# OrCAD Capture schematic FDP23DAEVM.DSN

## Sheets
1 PAGE3: size A; title: Adapter board-Power
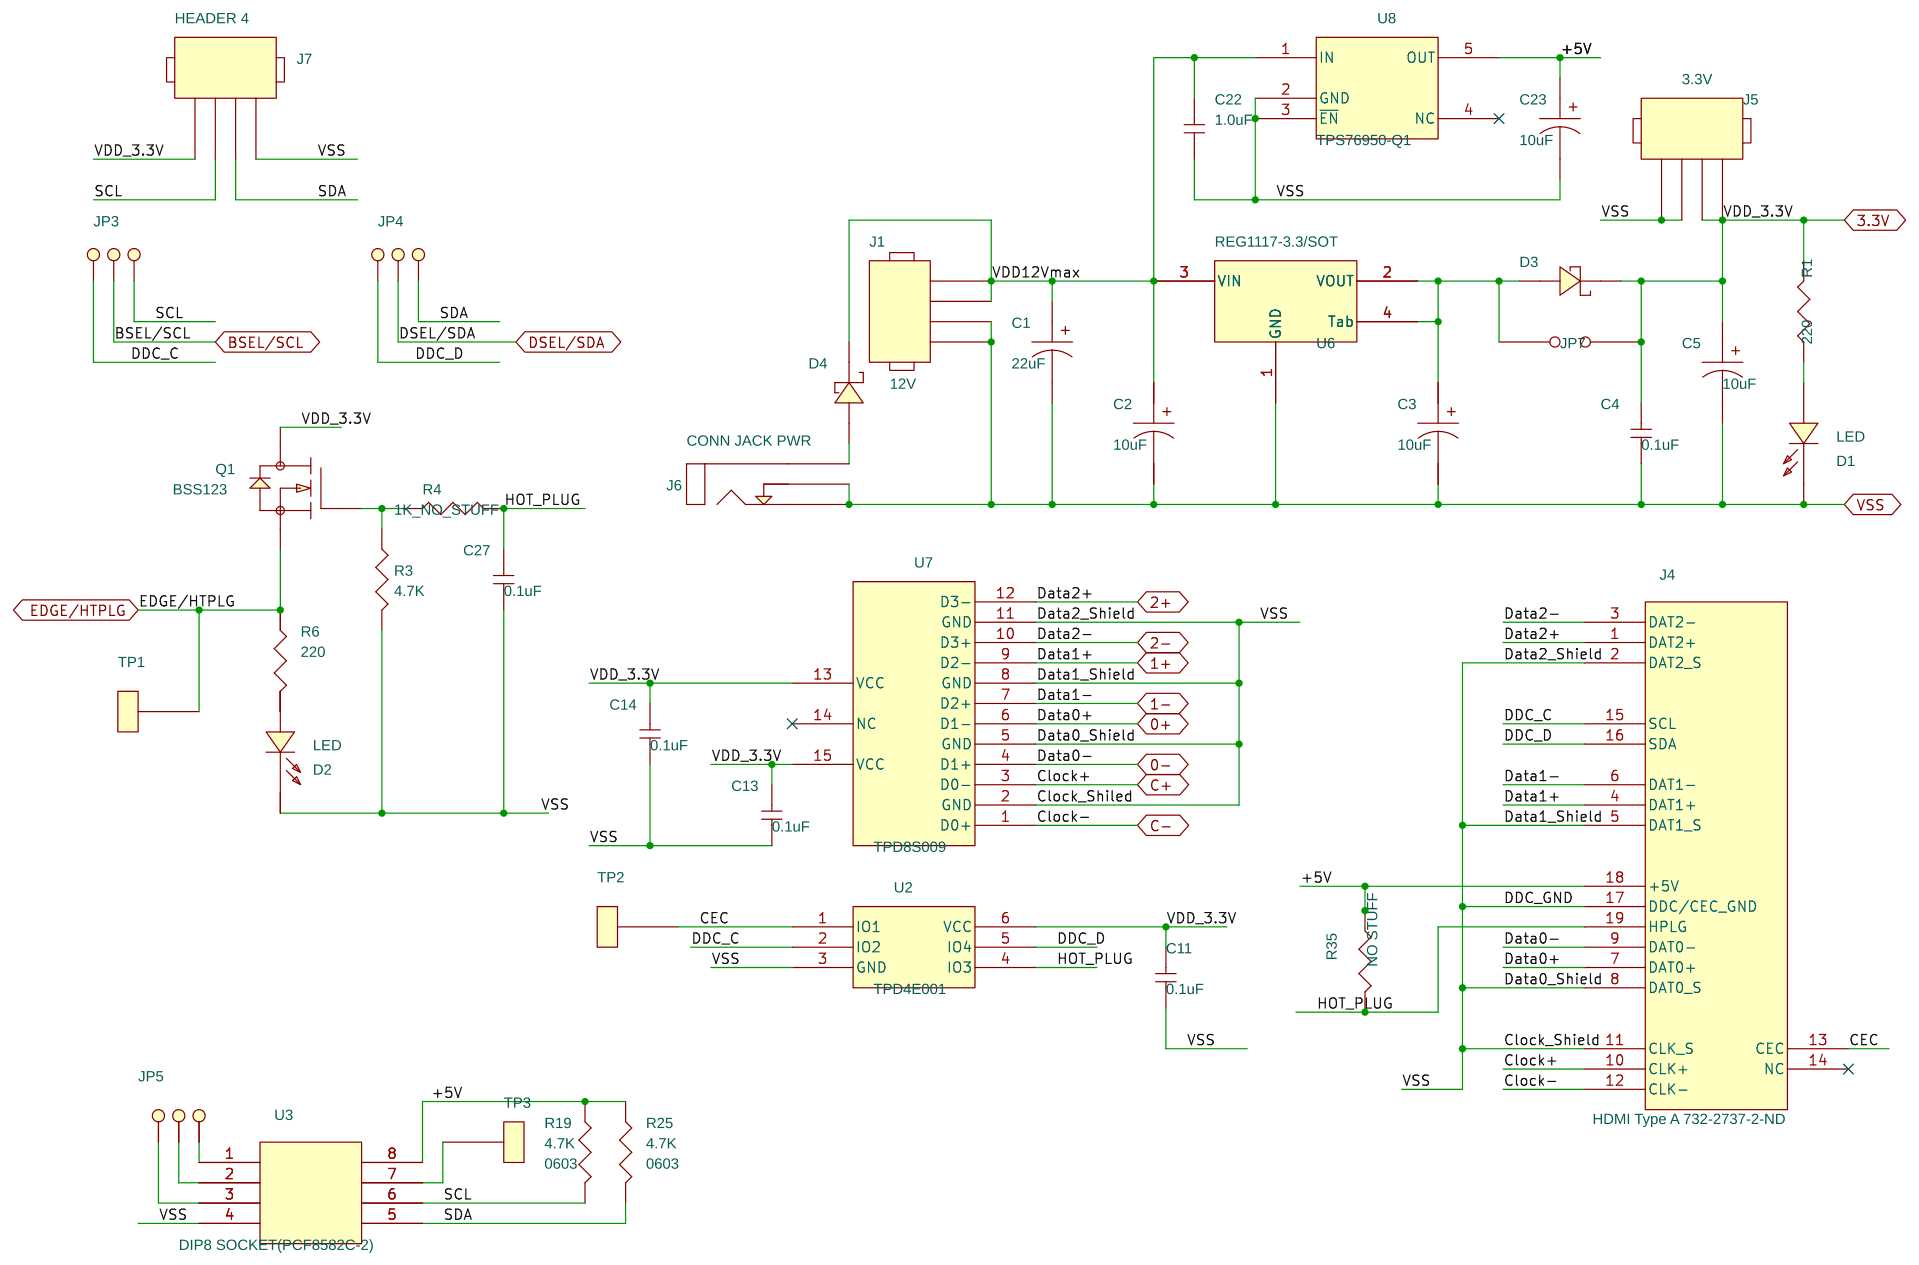
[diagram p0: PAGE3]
2 PAGE2: size A; title: Adapter board- DS90CF386
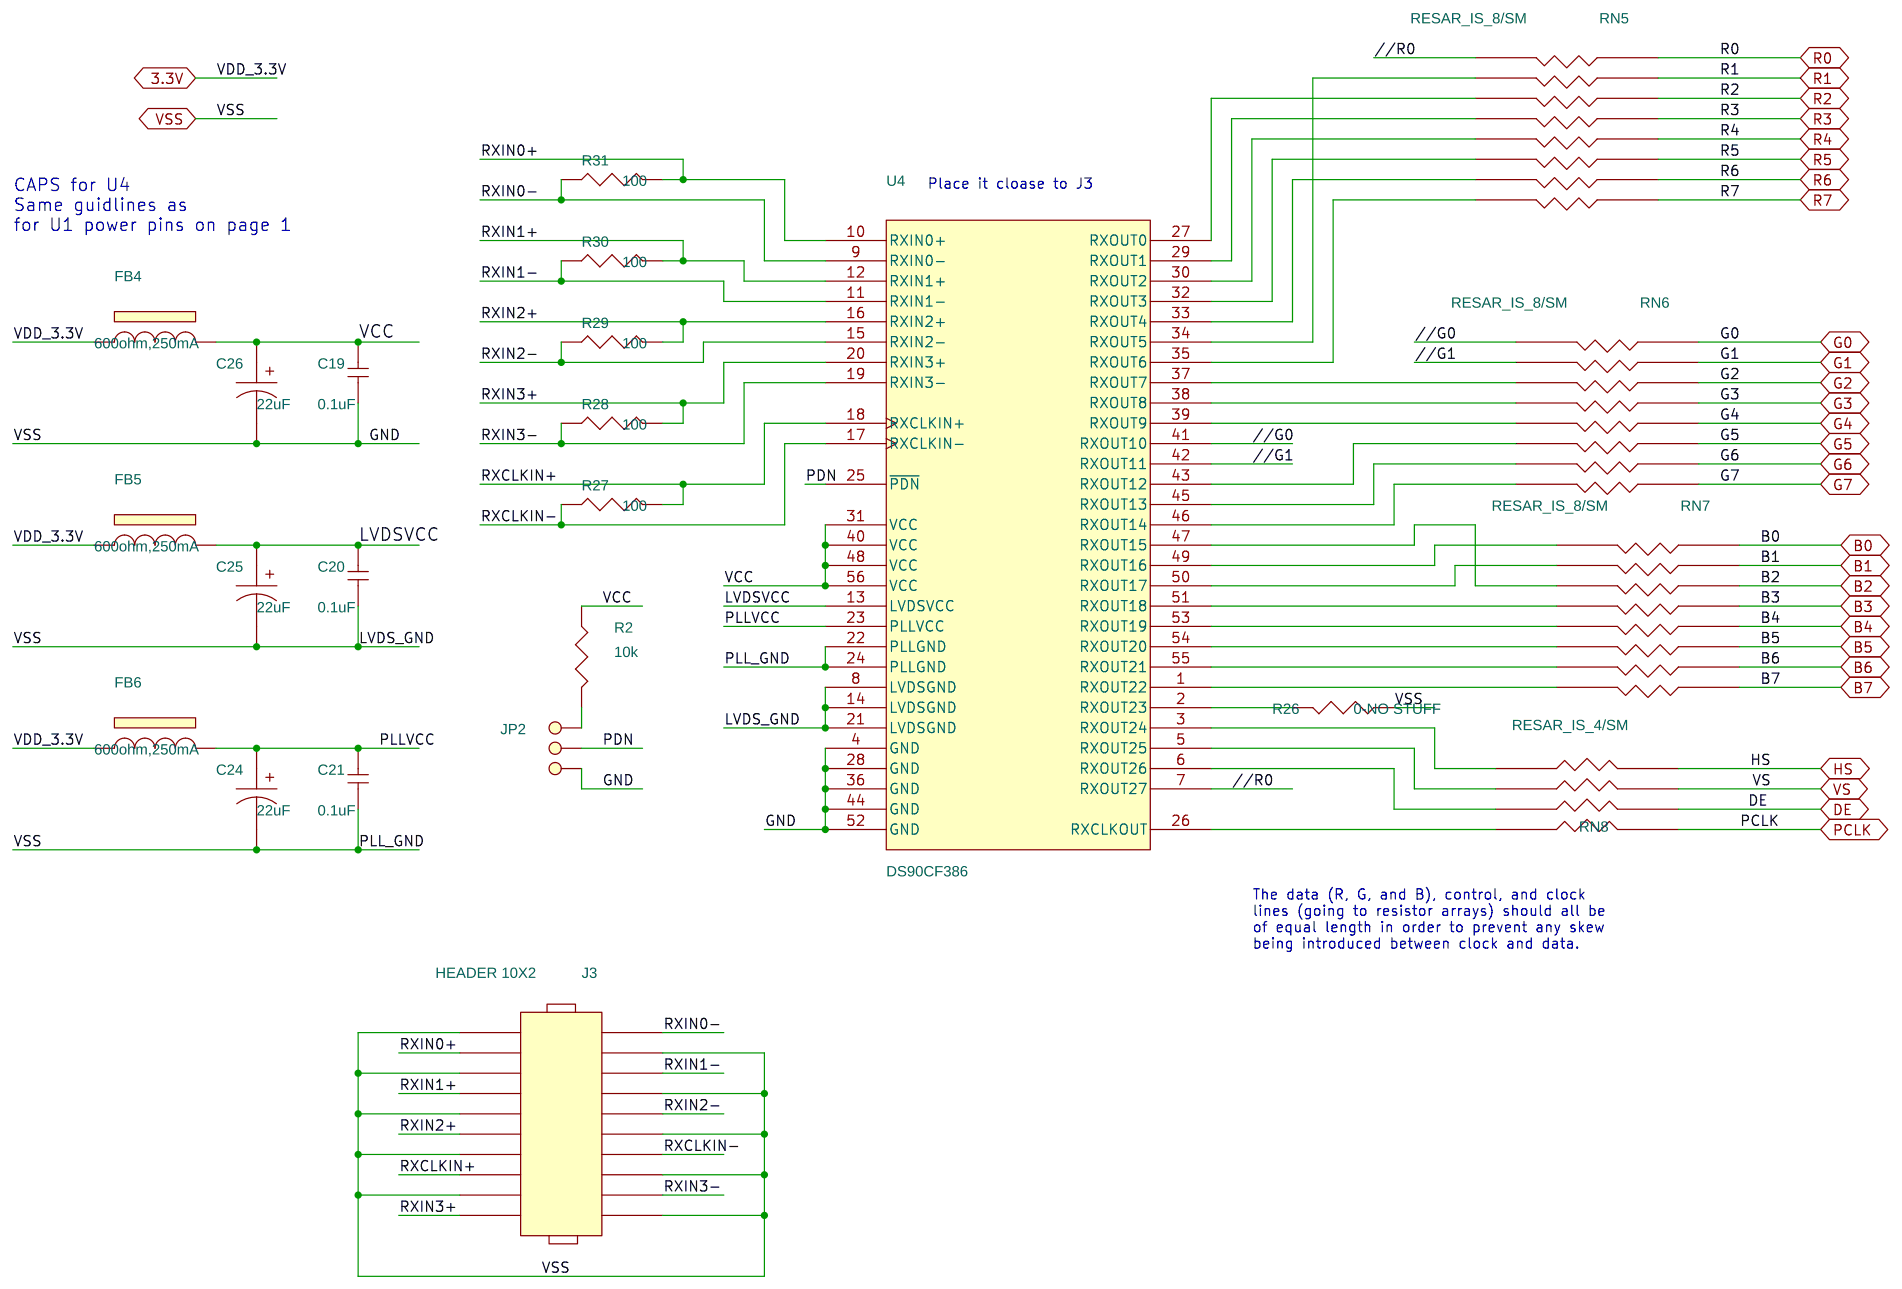
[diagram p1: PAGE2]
3 PAGE1: size B; title: Adapter Board-TFP410
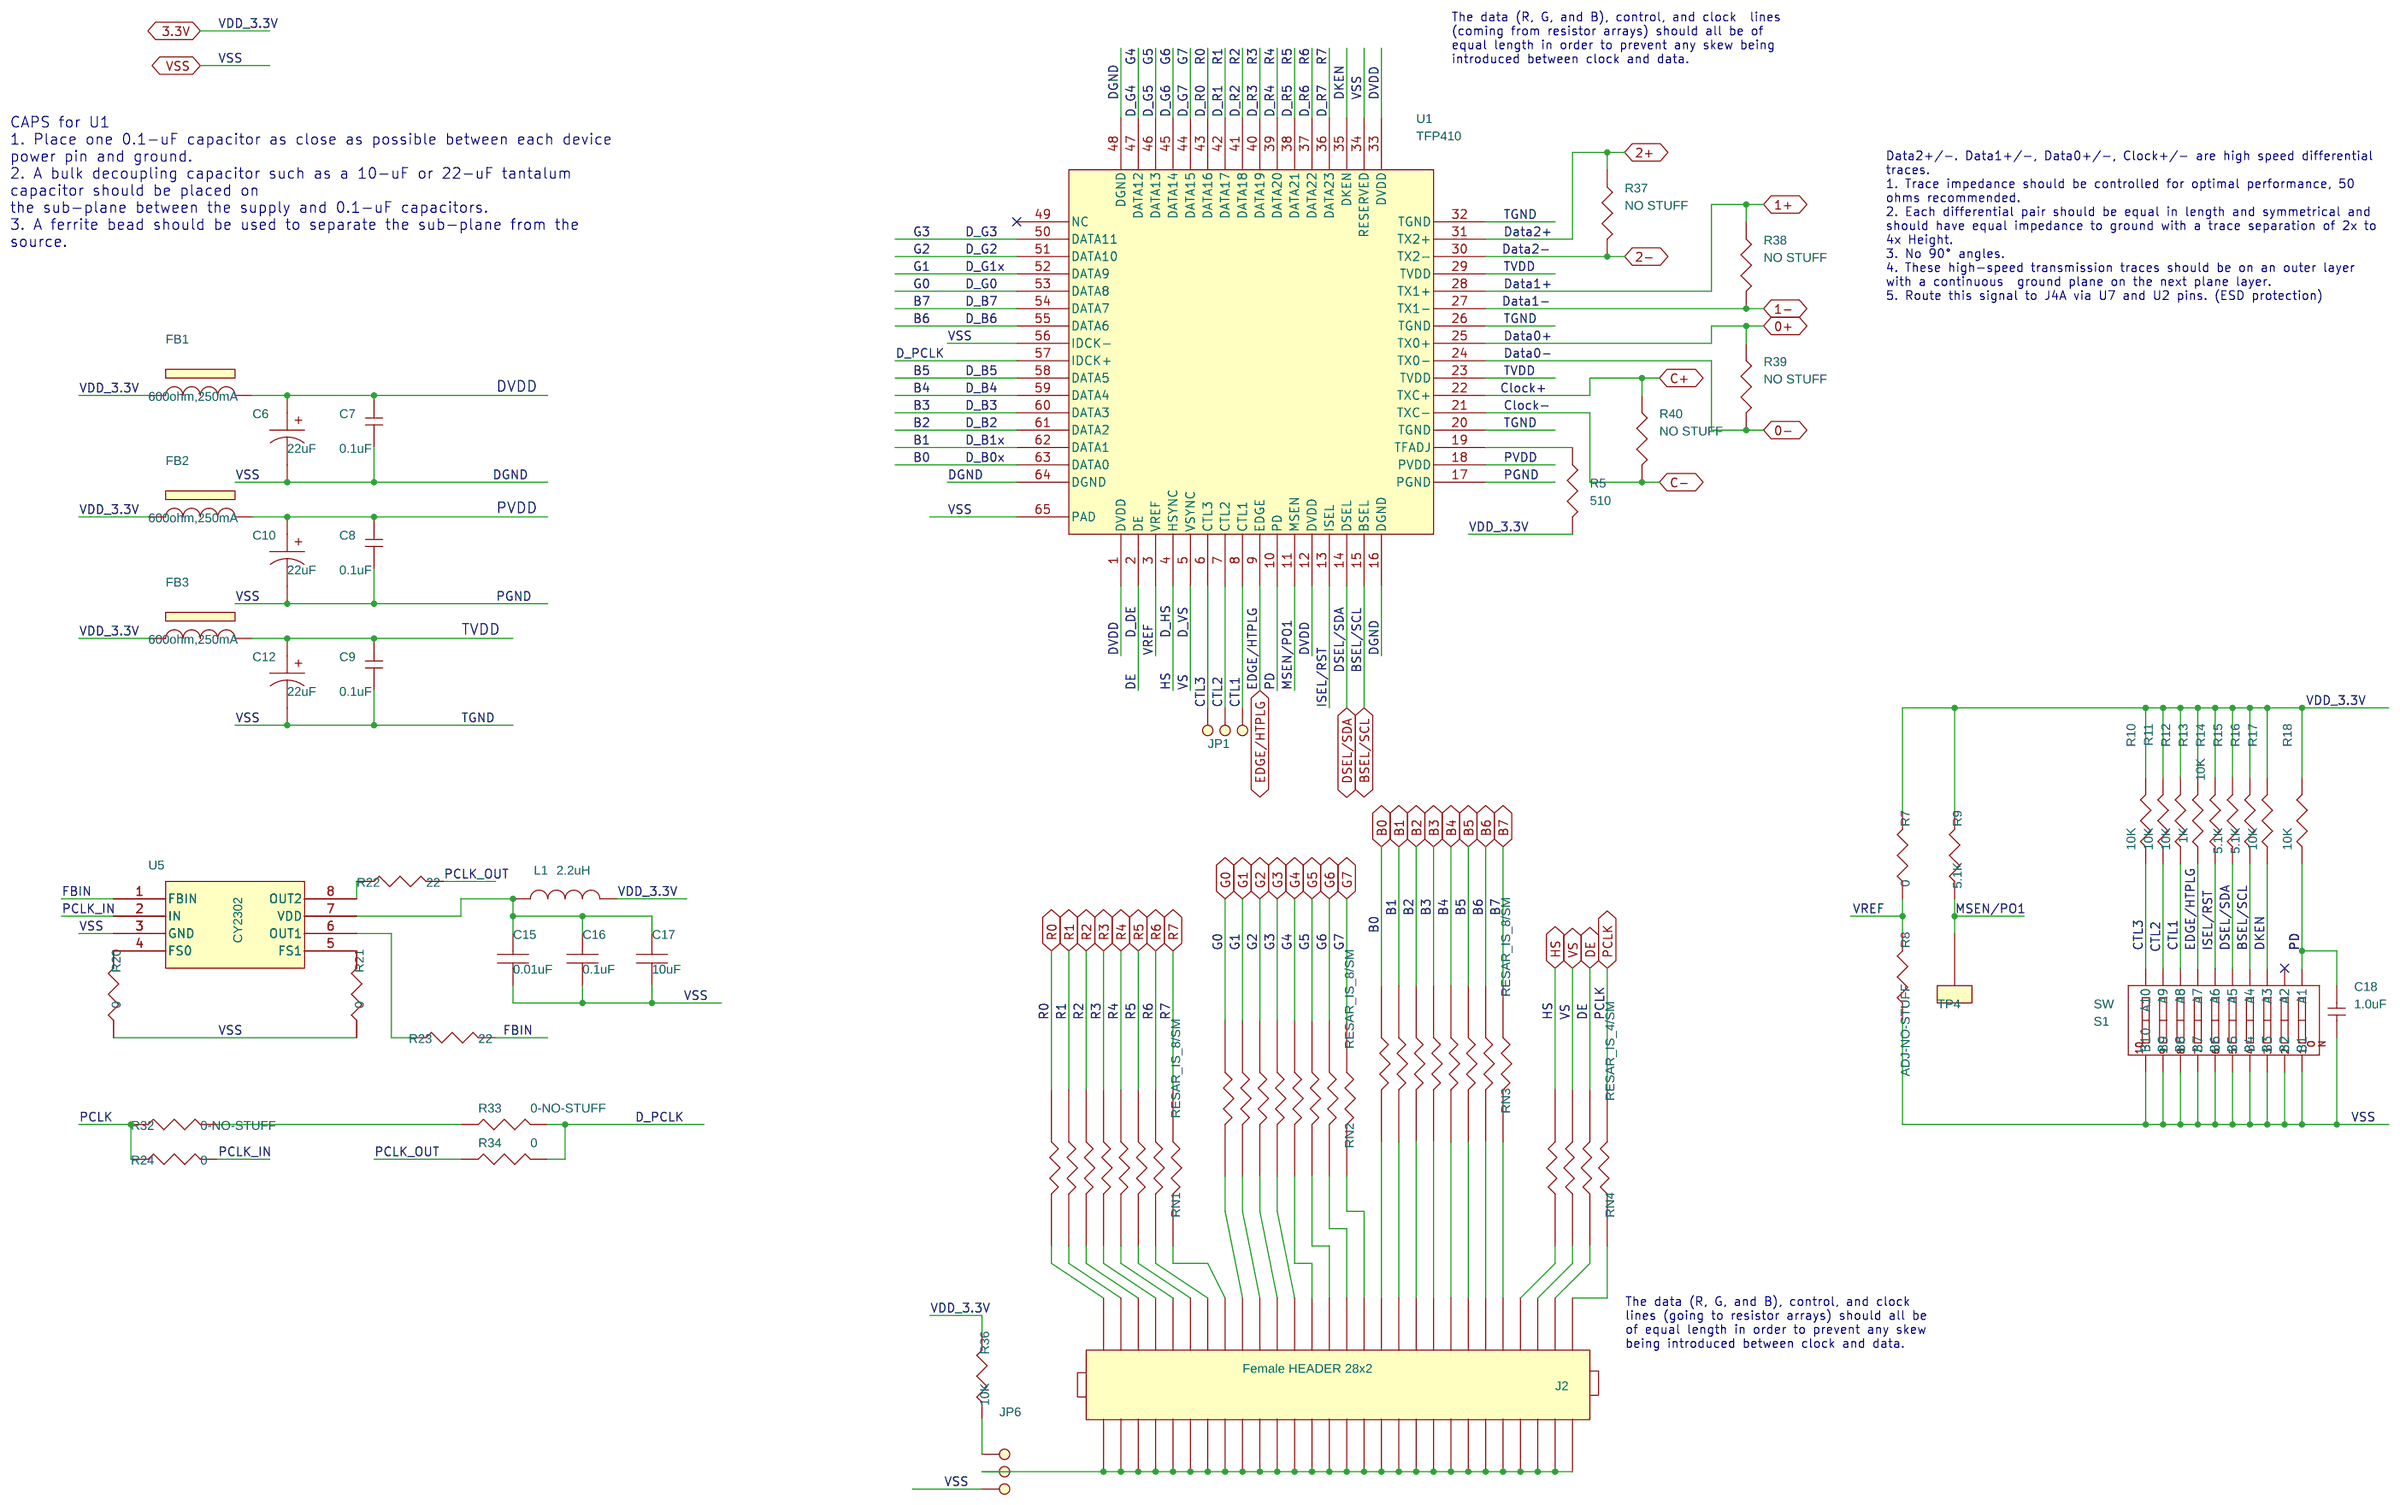
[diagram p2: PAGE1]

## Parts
sheet PAGE1
C6  22uF  [1206]
C7  0.1uF  [0201]
C8  0.1uF  [0201]
C9  0.1uF  [0201]
C10  22uF  [1206]
C12  22uF  [1206]
C15  0.01uF  [0603]
C16  0.1uF  [0603]
C17  10uF  [0612]
C18  1.0uF  [0402]
FB1  600ohm,250mA  [0402]
FB2  600ohm,250mA  [0402]
FB3  600ohm,250mA  [0402]
J2  Female HEADER 28x2  [HEADER_28X2_female]
JP1  3-Pin Header  [Header_3P]
JP6  3-Pin Header  [Header_3P]
L1  2.2uH  [1007]
R5  510  [0402]
R7  0  [0402]
R8  ADJ-NO-STUFF  [0603]
R9  5.1K  [0402]
R10  10K  [0402]
R11  10K  [0402]
R12  10K  [0402]
R13  1K  [0402]
R14  10K  [0402]
R15  5.1K  [0402]
R16  5.1K  [0402]
R17  10K  [0402]
R18  10K  [0402]
R20  0  [0402]
R21  0  [0402]
R22  22  [0402]
R23  22  [0402]
R24  0  [0402]
R32  0-NO-STUFF  [0402]
R33  0-NO-STUFF  [0402]
R34  0  [0402]
R36  10K  [0402]
R37  NO STUFF  [0201]
R38  NO STUFF  [0201]
R39  NO STUFF  [0201]
R40  NO STUFF  [0201]
RN1  RESAR_IS_8/SM  [RN_1506]
RN2  RESAR_IS_8/SM  [RN_1506]
RN3  RESAR_IS_8/SM  [RN_1506]
RN4  RESAR_IS_4/SM  [RN_0804]
S1  SW  [DIP_SW_10POS]
TP4  TEST POINT  [TEST_POINT]
U1  TFP410  [64L_TQFP]
U5  CY2302  [8_SOIC]
sheet PAGE2
C19  0.1uF  [0201]
C20  0.1uF  [0201]
C21  0.1uF  [0201]
C24  22uF  [1206]
C25  22uF  [1206]
C26  22uF  [1206]
FB4  600ohm,250mA  [0402]
FB5  600ohm,250mA  [0402]
FB6  600ohm,250mA  [0402]
J3  HEADER 10X2  [HEADER_10X2_Female]
JP2  3-Pin Header  [Header_3P]
R2  10k  [0402]
R26  0-NO STUFF  [0603]
R27  100  [0402]
R28  100  [0402]
R29  100  [0402]
R30  100  [0402]
R31  100  [0402]
RN5  RESAR_IS_8/SM  [RN_1506]
RN6  RESAR_IS_8/SM  [RN_1506]
RN7  RESAR_IS_8/SM  [RN_1506]
RN8  RESAR_IS_4/SM  [RN_0804]
U4  DS90CF386  [56_TSSOP]
sheet PAGE3
C1  22uF  [2917]
C2  10uF  [2312]
C3  10uF  [2312]
C4  0.1uF  [0805]
C5  10uF  [2312]
C11  0.1uF  [0603]
C13  0.1uF  [0603]
C14  0.1uF  [0603]
C22  1.0uF  [0402]
C23  10uF  [2312]
C27  0.1uF  [0201]
D1  LED  [0603_LED]
D2  LED  [0603_LED]
D3  DIODE SCHOTTKY  [SMA]
D4  DIODE SCHOTTKY  [SMA]
J1  12V  [Header_4P]
J4  HDMI Type A 732-2737-2-ND  [HDMIconn]
J5  3.3V  [Header_4P]
J6  CONN JACK PWR  [DC_PWR_JACK]
J7  HEADER 4  [Header_4P]
JP3  3-Pin Header  [Header_3P]
JP4  3-Pin Header  [Header_3P]
JP5  3-Pin Header  [Header_3P]
JP7  JUMPER  [Header_2P]
Q1  BSS123  [SOT_23]
R1  220  [0402]
R3  4.7K  [0402]
R4  1K_NO_STUFF  [0402]
R6  220  [0402]
R19  4.7K  [0603]
R25  4.7K  [0603]
R35  NO STUFF  [0603]
TP1  TEST POINT  [TEST_POINT]
TP2  TEST POINT  [TEST_POINT]
TP3  TEST POINT  [TEST_POINT]
U2  TPD4E001  [6_USON]
U3  DIP8 SOCKET(PCF8582C-2)  [DIP8]
U6  REG1117-3.3/SOT  [TO_263_4]
U7  TPD8S009  [15_SON]
U8  TPS76950-Q1  [SOT_23_5]

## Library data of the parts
C6 C10 C12 C24-C26 = CAPACITOR_POL_1: Comments: CAP TANT 22UF 10V 10% SMD; Digi-Key P/N: 718-1473-1-ND; Lead Free?: YES; Part number: TR3A226K010C0800; RoHS Compliant?: YES; Vendor: Vishay/Sprague
C7-C9 C19-C21 C27 = C: Comments: CAP CER .1UF 6.3V X5R 10% 0201; Digi-Key P/N: 445-1796-1-ND; Lead Free?: YES; Part number: C0603X5R0J104K; RoHS Compliant?: YES; Vendor: TDK Corporation
C15 = CAPACITOR_NON-POL_0: Comments: CAP CERAMIC .01UF 100V X7R 0603; Digi-Key P/N: 399-3189-1-ND; Lead Free?: YES; Part number: C0603C103K1RACTU; RoHS Compliant?: YES; Vendor: KEMET
C16 = CAPACITOR_NON-POL_0: Comments: CAP CER .1UF 50V X7R 0603; Digi-Key P/N: 490-4779-1-ND; Lead Free?: YES; Part number: GCM188R71H104KA57D; RoHS Compliant?: YES; Vendor: Murata
C17 = CAPACITOR_NON-POL_1: Comments: CAP CER 10UF 6.3V X5R 0612; Digi-Key P/N: 445-4072-1-ND; Lead Free?: YES; Part number: C1632X5R0J106M; RoHS Compliant?: YES; Vendor: TDK
C18 C22 = C: Comments: CAP CERAMIC 1UF 10V X5R 0402; Digi-Key P/N: PCC2364CT-ND; Lead Free?: YES; Part number: ECJ-0EB1A105M; RoHS Compliant?: YES; Vendor: Panasonic
FB1-FB6 = INDUCTOR_FERRITE: Comments: FERRITE BEAD 600 OHM 0402; Digi-Key P/N: 587-1839-1-ND; Lead Free?: YES; Part Number: BK1005HM601-T; RoHS Compliant?: YES; Vendor: Taiyo Yuden
J2 = HEADER_28x2: Comments: CONN HEADER FMAL 56PS .1" DL TIN; Digi-Key P/N: S7096-ND; Part number: PPTC282LFBN-RC; Vendor: Sullins Connector Solutions
JP1 JP6 = JUMPER_12: Comments: CONN HEADER VERT .100 3POS 15AU; Digi-Key P/N: A26545-ND; Lead Free?: YES; Part number: 87224-3; RoHS Compliant?: YES; Vendor: TE Connectivity
L1 = INDUCTOR: Comments: INDUCTOR 2.2UH 20% 1007 SMD; Digi-Key P/N: 587-1954-2-ND; Lead Free?: YES; Part number: BRL2518T2R2M; RoHS Compliant?: YES; Vendor: Taiyo Yuden
R5 = R_14: Comments: RES 510 OHM 1/10W 1% 0402 SMD; Digi-Key P/N: P510LCT-ND; Lead Free?: YES; Part number: ERJ-2RKF5100X; RoHS Compliant?: YES; Vendor: Panasonic
R7 R20 R21 = R_6: Comments: RES ZERO OHM 1/16W 5% 0402 SMD.; Digi-Key P/N: P0.0JTR-ND; Lead Free?: YES; Part number: ERJ-2GEJ0R00X; RoHS Compliant?: YES; Vendor: Panasonic
R8 = R_6: Comments: 0603 SMD- DO NOT STUFF; Digi-Key P/N: NO STUFF; Lead Free?: YES; Part number: NO STUFF; RoHS Compliant?: YES; Vendor: Panasonic
R9 R15 R16 = R_6: Comments: RES 5.1K OHM 1/10W 5% 0402 SMD; Digi-Key P/N: P5.1KJTR-ND; Lead Free?: YES; Part number: ERJ-2GEJ512X; RoHS Compliant?: YES; Vendor: Panasonic
R10-R12 R17 R18 R36 = R_6: Comments: RES 10K OHM 1/10W 5% 0402 SMD; Digi-Key P/N: P10KJCT-ND; Lead Free?: YES; Part number: ERJ-2GEJ103X; RoHS Compliant?: YES; Vendor: Panasonic
R13 = R_6: Comments: RES 1K OHM 1/10W 5% 0402 SMD; Digi-Key P/N: P1.0KJTR-ND; Lead Free?: YES; Part number: ERJ-2GEJ102X; RoHS Compliant?: YES; Vendor: Panasonic
R14 = R_1: Comments: RES 10K OHM 1/10W 5% 0402 SMD; Digi-Key P/N: P10KJCT-ND; Lead Free?: YES; Part number: ERJ-2GEJ103X; RoHS Compliant?: YES; Vendor: Panasonic
R22 = R_8: Comments: RES 22.0 OHM 1/10W 1% 0402 SMD; Digi-Key P/N: P22.0LCT-ND; Lead Free?: YES; Part number: ERJ-2RKF22R0X; RoHS Compliant?: YES; Vendor: Panasonic
R23 = R_9: Comments: RES 22.0 OHM 1/10W 1% 0402 SMD; Digi-Key P/N: P22.0LCT-ND; Lead Free?: YES; Part number: ERJ-2RKF22R0X; RoHS Compliant?: YES; Vendor: Panasonic
R24 = R_10: Comments: RES ZERO OHM 1/16W 5% 0402 SMD.; Digi-Key P/N: P0.0JTR-ND; Lead Free?: YES; Part number: ERJ-2GEJ0R00X; RoHS Compliant?: YES; Vendor: Panasonic
R32 = R_11: Comments: RES ZERO OHM  5% 0402 SMD - DO NOT STUFF; Digi-Key P/N: P0.0JTR-ND; Lead Free?: YES; Part number: ERJ-2GEJ0R00X-NO STUFF; RoHS Compliant?: YES; Vendor: Panasonic
R33 = R_12: Comments: RES ZERO OHM 1/16W 5% 0402 SMD.; Digi-Key P/N: P0.0JTR-ND; Lead Free?: YES; Part number: ERJ-2GEJ0R00X-NO STUFF; RoHS Compliant?: YES; Vendor: Panasonic
R34 = R_13: Comments: RES ZERO OHM 1/16W 5% 0402 SMD.; Digi-Key P/N: P0.0JTR-ND; Lead Free?: YES; Part number: ERJ-2GEJ0R00X; RoHS Compliant?: YES; Vendor: Panasonic
R37-R40 = RESISTOR: Comments: 0201 SMD- DO NOT STUFF; Digi-Key P/N: P100AGTR-ND; Part number: ERJ-1GEJ101C-NO STUFF; Vendor: Panasonic
RN1-RN3 RN5-RN7 = RESAR_IS_8_SM: Comments: RES ARRAY ZERO OHM 8 RES 1506; Digi-Key P/N: Y1000TR-ND; Part number: EXB-2HVR000V
RN4 RN8 = RESAR_IS_4_SM: Comments: RES ARRAY ZERO OHM 4 RES 0804; Digi-Key P/N: Y7000TR-ND; Part number: EXB-28VR000X
S1 = SW_SMD-10_0: Comments: SWITCH DIP EXTENDED UNSEAL 10POS; Digi-Key P/N: GH7195-ND; Part number: 78B10T
TP1-TP4 = TEST_POINT: Comments: TEST POINT PC MULTI PURPOSE RED; Digi-Key P/N: 5010K-ND- DO NOT STUFF; Part number: 5010-NO STUFF
U1 = TFP410_0: Comments: IC TRANSMITTER DIGITAL 64-HTQFP; Digi-Key P/N: 296-12666-ND; Lead Free?: YES; Part number: TFP410PAP; RoHS Compliant?: YES; Vendor: TI
U5 = PKG_SOIC8_0: Comments: IC CLK FREQ MULTI/ZDB 2OUT 8SOIC; Digi-Key P/N: 428-2188-5-ND; Lead Free?: YES; Part number: CY2302SXI-1; RoHS Compliant?: YES; Vendor: Cirrus Logic Inc
J3 = HEADER_10X2: Comments: CONN RECEPT 20POS .100 VERT DUAL; Digi-Key P/N: A26460-ND; Part number: 1-534206-0
JP2-JP5 = JUMPER_12: Comments: CONN HEADER VERT .100 3POS 15AU; Digi-Key P/N: A26545-ND; Lead Free?: YES; Part number: 87224-3; RoHS Compliant?: YES; Vendor: AMP/Tyco
R2 = R_7: Comments: RES 10K OHM 1/10W 5% 0402 SMD; Digi-Key P/N: P10KJCT-ND; Lead Free?: YES; Part number: ERJ-2GEJ103X; RoHS Compliant?: YES; Vendor: Panasonic
R26 = R_5: Comments: 0603 SMD- DO NOT STUFF; Digi-Key P/N: NO STUFF; Lead Free?: YES; Part number: NO STUFF; RoHS Compliant?: YES; Vendor: Panasonic
R27-R30 = RESISTOR: Comments: RES 100 OHM 1/10W 5% 0402 SMD; Digi-Key P/N: P100JTR-ND; Part number: ERJ-2GEJ101X; Vendor: Panasonic
R31 = RESISTOR_0: Comments: RES 100 OHM 1/10W 5% 0402 SMD; Digi-Key P/N: P100JTR-ND; Part number: ERJ-2GEJ101X; Vendor: Panasonic
U4 = DS90CF384_SO_1: Comments: IC RCVR LVDS FPD 24BIT 56-TSSOP; Digi-Key P/N: DS90CF386MTD/NOPB-ND; Part number: DS90CF386MTD/NOPB; Vendor: TI
C1 = CAPACITOR_POL_1: Comments: CAP TANT 22UF 25V 20% 2917; Digi-Key P/N: 493-2391-2-ND; Lead Free?: YES; Part number: F931E226MNC; RoHS Compliant?: YES; Vendor: Nichicon
C2 C3 C5 C23 = CAPACITOR_POL_1: Comments: CAP TANT 10UF 25V 20% 2312; Digi-Key P/N: 718-1044-1-ND; Lead Free?: YES; Part number: 293D106X0025C2TE3; RoHS Compliant?: YES; Vendor: Vishay/Sprague
C4 = C: Comments: CAP CER 0.1UF 25V 10% X7R 0805; Digi-Key P/N: 478-3755-1-ND; Lead Free?: YES; Part number: 08053C104KAT2A; RoHS Compliant?: YES; Vendor: AVX Corporation
C11 = C: Comments: CAP CER .1UF 50V X7R 0603; Digi-Key P/N: 490-4779-1-ND; Lead Free?: YES; PSpiceTemplate: C^@REFDES %1 %2 ?TOLERANCE|C^@REFDES| @VALUE ?IC/IC=@IC/ ?TOLERANCE|\n.model C^@REFDES CAP C=1 DEV=@TOLERANCE%|; Part number: GCM188R71H104KA57D; RoHS Compliant?: YES; Vendor: Murata
C13 C14 = C: Comments: CAP CER .1UF 50V X7R 0603; Digi-Key P/N: 490-4779-1-ND; Lead Free?: YES; Part number: GCM188R71H104KA57D; RoHS Compliant?: YES; Vendor: Murata
D1 = LED: Comments: LED GREEN CLEAR THIN 0603 SMD; Digi-Key P/N: 160-1443-2-ND; Part number: LTST-C191GKT; Vendor: Lite-On Inc
D2 = LED: Comments: LED SUPER RED CLR THIN 0603 SMD; Digi-Key P/N: 160-1447-2-ND; Part number: LTST-C191KRKT; Vendor: Lite-On Inc
D3 D4 = DIODE_SCHOTTKY: Comments: DIODE SCHOTTKY 10V 2A SMA; Digi-Key P/N: MBRA210LT3GOSTR-ND; Part number: MBRA210LT3G; Vendor: ON semi
J1 J5 J7 = HEADER_4: Comments: CONN HEADER 4POS .100 VERT GOLD; Digi-Key P/N: WM2702-ND; Part number: 0022112042; Vendor: Molex Inc
J4 = CONN_HDMI_0: Comments: CONN HDMI RECPT 19POS SMT R/A; Digi-Key P/N: 609-4614-2-ND; Part number: 10029449-111RLF; Vendor: FCI
J6 = CONN_JACK_PWR: Comments: CONN POWER JACK 2.1MM; Digi-Key P/N: CP-002A-ND; Part number: PJ-002A; Vendor: CUI Inc
JP7 = JUMPER_6: Comments: CONN HEADER VERT .100 2POS 30AU; Digi-Key P/N: A26542-ND; Part number: 87220-2; Vendor: TE Connectivity
Q1 = BSS123_0: Comments: MOSFET N-CH 100V 170MA SOT-23; Digi-Key P/N: BSS123LT1GOSTR-ND; Part number: BSS123LT1G; Vendor: ON semi
R1 = R_4: Comments: RES 220 OHM 1/10W 5% 0402 SMDSMD; Digi-Key P/N: P220JTR-ND; Lead Free?: YES; Part number: ERJ-2GEJ221X; RoHS Compliant?: YES; Vendor: Panasonic
R3 = R_6: Comments: RES 4.7K OHM 1/10W 5% 0402 SMD SMD; Digi-Key P/N: P4.7KJTR-ND; Lead Free?: YES; Part number: ERJ-2GEJ472X; RoHS Compliant?: YES; Vendor: Panasonic; size: 0603
R4 = R_6: Comments: RES 1K OHM 1/10W 5% 0402 SMD; Digi-Key P/N: P1.0KJTR-ND; Lead Free?: YES; Part number: ERJ-2GEJ102X; RoHS Compliant?: YES; Vendor: Panasonic; size: 0603
R6 = R_6: Comments: RES 220 OHM 1/10W 5% 0402 SMD SMD; Digi-Key P/N: P220JTR-ND; Lead Free?: YES; Part number: ERJ-2GEJ221X; RoHS Compliant?: YES; Vendor: Panasonic; size: 0603
R19 = R_6: Comments: RES 4.7K OHM 1/10W 5% 0603 SMD; Digi-Key P/N: P4.7KGCT-ND; Lead Free?: YES; Part number: ERJ-3GEYJ472V; RoHS Compliant?: YES; Vendor: Panasonic
R25 = R_0: Comments: RES 4.7K OHM 1/10W 5% 0603 SMD; Digi-Key P/N: P4.7KGCT-ND; Lead Free?: YES; Part number: ERJ-3GEYJ472V; RoHS Compliant?: YES; Vendor: Panasonic
R35 = R_6: Comments: 0603 SMD NO STUFF; Lead Free?: YES; RoHS Compliant?: YES; Vendor: Panasonic
U2 = TMS4C1070_8: Comments: IC ESD-PROT ARRAY 4CH 6USON; Digi-Key P/N: 296-30280-2-ND; Part number: TPD4E001DPKR; Vendor: TI
U3 = DIP8_SOCKET: Comments: SOCKET IC OPEN FRAME 8POS .3"; Digi-Key P/N: 3M5473-ND; Lead Free?: YES; Part number: 4808-3004-CP; RoHS Compliant?: YES; Vendor: 3M
U6 = REG1117_SOT_2: Comments: IC REG LDO 3.3V .8A D2PAK-3; Digi-Key P/N: 296-15941-2-ND; Part number: REG1117F-3.3/500; Vendor: TI
U7 = TMS4C1070_7: Comments: IC 8CH ESD PROTECTION 15-SON; Digi-Key P/N: 296-23829-2-ND; Part number: TPD8S009DSMR; Vendor: TI
U8 = TPS7133Q_HSOP_3: Comments: IC REG LDO 5V .1A SOT-23-5; Digi-Key P/N: 296-2761-2-ND; Part number: TPS76950DBVT; Vendor: TI

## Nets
3.3V: C4.2 C5.1 C11.2 C13.2 C14.2 D3.2(CATHODE) FB1.1 FB2.1 FB3.1 FB4.1 FB5.1 FB6.1 J5.3 J5.4 J7.1 JP7.2 L1.2 Q1.3(DRAIN) R1.2 R5.1 R7.2 R9.2 R10.2 R11.2 R12.2 R13.2 R14.2 R15.2 R16.2 R17.2 R18.2 R36.2 U2.6(VCC) U7.13(VCC) U7.15(VCC)
+5V: C23.1 J4.18(+5V) R19.1 R25.1 R35.1 U3.8 U8.5(OUT)
DVDD: C6.1 C7.2 FB1.2 U1.1(DVDD) U1.12(DVDD) U1.33(DVDD)
PVDD: C8.2 C10.1 FB2.2 U1.18(PVDD)
VCC: C19.2 C26.1 FB4.2 R2.1 U4.31(VCC) U4.40(VCC) U4.48(VCC) U4.56(VCC)
VDD12Vmax: C1.1 C2.1 C22.2 D4.2(CATHODE) J1.1 J1.2 U6.3(VIN) U8.1(IN)
VSS: C1.2 C2.2 C3.2 C4.1 C5.2 C6.2 C7.1 C8.1 C9.1 C10.2 C11.1 C12.2 C13.1 C14.1 C15.2 C16.2 C17.2 C18.1 C19.1 C20.1 C21.1 C22.1 C23.2 C24.2 C25.2 C26.2 C27.1 D1.2(CATHODE) D2.2(CATHODE) J1.3 J1.4 J3.2 J3.3 J3.6 J3.7 J3.10 J3.11 J3.14 J3.15 J3.18 J3.19 J4.2(DAT2_S) J4.5(DAT1_S) J4.8(DAT0_S) J4.11(CLK_S) J4.17(DDC/CEC_GND) J5.1 J5.2 J6.2 J6.3 J7.4 JP2.3 JP6.1 R3.2 R8.1 R20.1 R21.1 R26.1 S1.2(B1) S1.4(B2) S1.6(B3) S1.8(B4) S1.10(B5) S1.12(B6) S1.14(B7) S1.16(B8) S1.18(B9) S1.20(B10) U1.16(DGND) U1.17(PGND) U1.20(TGND) U1.26(TGND) U1.32(TGND) U1.34(RESERVED) U1.48(DGND) U1.56(IDCK-) U1.64(DGND) U1.65(PAD) U2.3(GND) U3.4 U4.4(GND) U4.8(LVDSGND) U4.14(LVDSGND) U4.21(LVDSGND) U4.22(PLLGND) U4.24(PLLGND) U4.28(GND) U4.36(GND) U4.44(GND) U4.52(GND) U5.3(GND) U6.1(GND) U7.2(GND) U7.5(GND) U7.8(GND) U7.11(GND) U8.2(GND) U8.3(~{EN})
0+: J4.7(DAT0+) R39.1 U1.25(TX0+) U7.6(D1-)
0-: J4.9(DAT0-) R39.2 U1.24(TX0-) U7.4(D1+)
1+: J4.4(DAT1+) R38.1 U1.28(TX1+) U7.9(D2-)
1-: J4.6(DAT1-) R38.2 U1.27(TX1-) U7.7(D2+)
2+: J4.1(DAT2+) R37.1 U1.31(TX2+) U7.12(D3-)
2-: J4.3(DAT2-) R37.2 U1.30(TX2-) U7.10(D3+)
//G0: RN6.8 U4.41(RXOUT10)
//G1: RN6.7 U4.42(RXOUT11)
//R0: RN5.8 U4.7(RXOUT27)
B0: RN3.8 RN7.9 U1.63(DATA0)
B1: RN3.7 RN7.10 U1.62(DATA1)
B2: RN3.6 RN7.11 U1.61(DATA2)
B3: RN3.5 RN7.12 U1.60(DATA3)
B4: RN3.4 RN7.13 U1.59(DATA4)
B5: RN3.3 RN7.14 U1.58(DATA5)
B6: RN3.2 RN7.15 U1.55(DATA6)
B7: RN3.1 RN7.16 U1.54(DATA7)
BSEL/SCL: JP3.2 R16.1 S1.7(A4) U1.15(BSEL)
C+: J4.10(CLK+) R40.1 U1.22(TXC+) U7.3(D0-)
C-: J4.12(CLK-) R40.2 U1.21(TXC-) U7.1(D0+)
CEC: J4.13(CEC) TP2.1 U2.1(IO1)
CTL1: JP1.3 R12.1 S1.15(A8) U1.8(CTL1)
CTL2: JP1.2 R11.1 S1.17(A9) U1.7(CTL2)
CTL3: JP1.1 R10.1 S1.19(A10) U1.6(CTL3)
D_PCLK: R33.1 R34.1 U1.57(IDCK+)
DDC_C: J4.15(SCL) JP3.3 U2.2(IO2)
DDC_D: J4.16(SDA) JP4.3 U2.5(IO4)
DE: RN4.3 RN8.6 U1.2(DE)
DKEN: R17.1 S1.5(A3) U1.35(DKEN)
DSEL/SDA: JP4.2 R15.1 S1.9(A5) U1.14(DSEL)
EDGE/HTPLG: Q1.2(SOURCE) R6.1 R13.1 S1.13(A7) TP1.1 U1.9(EDGE)
FBIN: R23.1 U5.1(FBIN)
G0: RN2.8 RN6.9 U1.53(DATA8)
G1: RN2.7 RN6.10 U1.52(DATA9)
G2: RN2.6 RN6.11 U1.51(DATA10)
G3: RN2.5 RN6.12 U1.50(DATA11)
G4: RN2.4 RN6.13 U1.47(DATA12)
G5: RN2.3 RN6.14 U1.46(DATA13)
G6: RN2.2 RN6.15 U1.45(DATA14)
G7: RN2.1 RN6.16 U1.44(DATA15)
HOT_PLUG: C27.2 J4.19(HPLG) R4.2 R35.2 U2.4(IO3)
HS: RN4.1 RN8.8 U1.4(HSYNC)
ISEL/RST: R14.1 S1.11(A6) U1.13(ISEL)
LVDSVCC: C20.2 C25.1 FB5.2 U4.13(LVDSVCC)
MSEN/PO1: R9.1 TP4.1 U1.11(MSEN)
PCLK: R24.2 R32.2 RN4.4 RN8.5
PCLK_IN: R24.1 U5.2(IN)
PCLK_OUT: R22.1 R34.2
PD: C18.2 R18.1 S1.1(A1) U1.10(PD)
PDN: JP2.2 U4.25(~{PDN})
PLLVCC: C21.2 C24.1 FB6.2 U4.23(PLLVCC)
R0: RN1.8 RN5.9 U1.43(DATA16)
R1: RN1.7 RN5.10 U1.42(DATA17)
R2: RN1.6 RN5.11 U1.41(DATA18)
R3: RN1.5 RN5.12 U1.40(DATA19)
R4: RN1.4 RN5.13 U1.39(DATA20)
R5: RN1.3 RN5.14 U1.38(DATA21)
R6: RN1.2 RN5.15 U1.37(DATA22)
R7: RN1.1 RN5.16 U1.36(DATA23)
RXCLKIN+: J3.16 R27.2 U4.18(RXCLKIN+)
RXCLKIN-: J3.13 R27.1 U4.17(RXCLKIN-)
RXIN0+: J3.4 R31.2 U4.10(RXIN0+)
RXIN0-: J3.1 R31.1 U4.9(RXIN0-)
RXIN1+: J3.8 R30.2 U4.12(RXIN1+)
RXIN1-: J3.5 R30.1 U4.11(RXIN1-)
RXIN2+: J3.12 R29.2 U4.16(RXIN2+)
RXIN2-: J3.9 R29.1 U4.15(RXIN2-)
RXIN3+: J3.20 R28.2 U4.20(RXIN3+)
RXIN3-: J3.17 R28.1 U4.19(RXIN3-)
SCL: J7.2 JP3.1 R19.2 U3.6
SDA: J7.3 JP4.1 R25.2 U3.5
TVDD: C9.2 C12.1 FB3.2 U1.23(TVDD) U1.29(TVDD)
VREF: R7.1 R8.2 U1.3(VREF)
VS: RN4.2 RN8.7 U1.5(VSYNC)
N14860968: J2.1 J2.3 J2.5 J2.7 J2.9 J2.11 J2.13 J2.15 J2.17 J2.19 J2.21 J2.23 J2.25 J2.27 J2.29 J2.31 J2.33 J2.35 J2.37 J2.39 J2.41 J2.43 J2.45 J2.47 J2.49 J2.51 J2.53 J2.55 JP6.2
N14861406: R5.2 U1.19(TFADJ)
N14862082: C15.1 C16.1 C17.1 L1.1 U5.7(VDD)
N15107145: JP2.1 R2.2
N15438976: D4.1(ANODE) J6.1
N15439034: C3.1 D3.1(ANODE) JP7.1 U6.2(VOUT) U6.4(Tab)
N15440280: JP5.1 U3.1
N15440284: JP5.2 U3.2
N15440292: JP5.3 U3.3
N15476881: D1.1(ANODE) R1.1
N15551732: Q1.1(GATE) R3.1 R4.1
N15559932: D2.1(ANODE) R6.2
N15593216: TP3.1 U3.7
N15691374: J2.14 RN1.15
N15691376: J2.12 RN1.14
N15691378: J2.10 RN1.13
N15691380: J2.4 RN1.10
N15691382: J2.8 RN1.12
N15691384: J2.2 RN1.9
N15691386: J2.6 RN1.11
N15693021: J2.16 RN1.16
N15693494: J2.24 RN2.12
N15693496: J2.22 RN2.11
N15693498: J2.20 RN2.10
N15693502: J2.18 RN2.9
N15693504: J2.30 RN2.15
N15693506: J2.28 RN2.14
N15693508: J2.26 RN2.13
N15694906: J2.50 RN4.8
N15694908: J2.52 RN4.7
N15694910: J2.54 RN4.6
N15694912: J2.56 RN4.5
N15695898: J2.42 RN3.13
N15695900: J2.44 RN3.14
N15695902: J2.40 RN3.12
N15695904: J2.46 RN3.15
N15695906: J2.48 RN3.16
N15695908: J2.38 RN3.11
N15695910: J2.36 RN3.10
N15695912: J2.34 RN3.9
N15696379: J2.32 RN2.16
N15736550: RN5.6 U4.27(RXOUT0)
N15737945: RN5.5 U4.29(RXOUT1)
N15738621: RN5.4 U4.30(RXOUT2)
N15739305: RN5.3 U4.32(RXOUT3)
N15741654: RN5.2 U4.33(RXOUT4)
N15742354: RN5.7 U4.34(RXOUT5)
N15743062: RN5.1 U4.35(RXOUT6)
N15744198: RN8.4 U4.26(RXCLKOUT)
N15747608: RN8.1 U4.3(RXOUT24)
N15748336: RN8.2 U4.5(RXOUT25)
N15750252: RN8.3 U4.6(RXOUT26)
N15750996: R26.2 U4.2(RXOUT23)
N15751370: RN7.1 U4.1(RXOUT22)
N15751746: RN7.2 U4.55(RXOUT21)
N15752124: RN7.3 U4.54(RXOUT20)
N15752504: RN7.4 U4.53(RXOUT19)
N15752886: RN7.5 U4.51(RXOUT18)
N15754502: RN7.7 U4.50(RXOUT17)
N15759288: RN7.8 U4.49(RXOUT16)
N15761170: RN7.6 U4.47(RXOUT15)
N15764711: RN6.1 U4.46(RXOUT14)
N15767513: RN6.2 U4.45(RXOUT13)
N15768326: RN6.3 U4.43(RXOUT12)
N15769147: RN6.6 U4.37(RXOUT7)
N15769559: RN6.5 U4.38(RXOUT8)
N15769973: RN6.4 U4.39(RXOUT9)
N15799422: R23.2 U5.6(OUT1)
N15814147: R32.1 R33.2
N15821065: R22.2 U5.8(OUT2)
N15926102: JP6.3 R36.1
N16355051: R21.2 U5.5(FS1)
N16355052: R20.2 U5.4(FS0)

Not connected (* = marked no-connect by the designer): J4 14(NC)*; S1 3(A2)*; U1 49(NC)*; U7 14(NC)*; U8 4(NC)*

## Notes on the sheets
sheet 2
- CAPS for U4
  Same guidlines as
  for U1 power pins on page 1
- Place it cloase to J3
- The data (R, G, and B), control, and clock
  lines (going to resistor arrays) should all be
  of equal length in order to prevent any skew
  being introduced between clock and data.
sheet 3
- The data (R, G, and B), control, and clock  lines
  (coming from resistor arrays) should all be of
  equal length in order to prevent any skew being
  introduced between clock and data.
- CAPS for U1
  1. Place one 0.1-uF capacitor as close as possible between each device
  power pin and ground.
  2. A bulk decoupling capacitor such as a 10-uF or 22-uF tantalum
  capacitor should be placed on
  the sub-plane between the supply and 0.1-uF capacitors.
  3. A ferrite bead should be used to separate the sub-plane from the
  source.
- Data2+/-. Data1+/-, Data0+/-, Clock+/- are high speed differential
  traces.
  1. Trace impedance should be controlled for optimal performance, 50
  ohms recommended.
  2. Each differential pair should be equal in length and symmetrical and
  should have equal impedance to ground with a trace separation of 2x to
  4x Height.
  3. No 90° angles.
  4. These high-speed transmission traces should be on an outer layer
  with a continuous  ground plane on the next plane layer.
  5. Route this signal to J4A via U7 and U2 pins. (ESD protection)
- The data (R, G, and B), control, and clock
  lines (going to resistor arrays) should all be
  of equal length in order to prevent any skew
  being introduced between clock and data.
